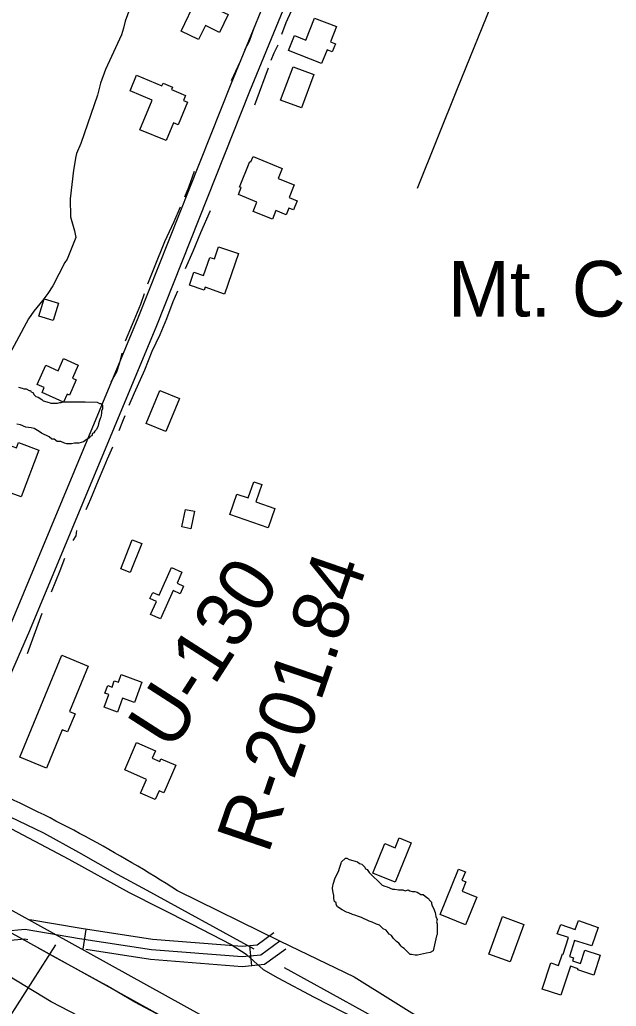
# Model space of a CAD drawing. Extents: x 3329332 to 3367211, y 631066 to 656469.
# Drawn here: x 3345355 to 3346246, y 646368 to 647841 of the extents above; entities that cross this region are included whole.
import ezdxf

# ---------------------------------------------------------------- set-up
doc = ezdxf.new("R2010")
doc.units = 0
for name, color, linetype in [('V-BLDG-OTLN', 7, 'Continuous'), ('V-FLOD-BASE', 7, 'Continuous'), ('V-LEVE-TOET', 7, 'Continuous'), ('V-RIVR-EDGE', 7, 'Continuous'), ('V-RIVR-RANG', 7, 'Continuous'), ('V-RIVR-RANG-IDEN', 7, 'Continuous'), ('V-ROAD-CNTR', 7, 'Continuous'), ('V-SITE-OTLN-IDEN', 7, 'Continuous'), ('V-SITE-VEGE', 7, 'Continuous'), ('V-SURV-LINE', 7, 'Continuous'), ('V-TOPO-SHOR', 7, 'Continuous')]:
    doc.layers.add(name, color=color, linetype=linetype)

msp = doc.modelspace()

# ---------------------------------------------------------------- linework, layer by layer
at = {"layer": 'V-BLDG-OTLN'}
for points in [[(3345595.9, 647824), (3345618.7, 647871.7), (3345666.3, 647848.9), (3345653.6, 647822.4), (3345632.2, 647832.6), (3345622.1, 647811.5)], [(3345756.7, 647795.1), (3345765.5, 647817.6), (3345782.6, 647810.9), (3345795.5, 647843.8), (3345828.1, 647831), (3345819.1, 647808.2), (3345826.5, 647805.3), (3345821.9, 647793.4), (3345814, 647796.4), (3345806, 647775.8)], [(3345744.7, 647721.2), (3345763.2, 647770.9), (3345794.5, 647759.3), (3345776, 647709.6)], [(3345534.5, 647677), (3345552.9, 647721.1), (3345519.8, 647735), (3345529.5, 647758.2), (3345567.3, 647742.4), (3345569, 647746.3), (3345583.3, 647740.3), (3345581.8, 647736.9), (3345602.6, 647728.2), (3345599.4, 647720.5), (3345605.7, 647717.9), (3345591.6, 647684.2), (3345584.7, 647687.1), (3345573.6, 647660.6)], [(3345703.5, 647636.9), (3345747.2, 647619.2), (3345741.1, 647604.1), (3345765, 647594.4), (3345757.4, 647575.6), (3345769.5, 647570.7), (3345764.1, 647557.1), (3345757.1, 647559.9), (3345753.1, 647549.7), (3345737.4, 647556.1), (3345732.4, 647543.5), (3345703.9, 647555), (3345709.4, 647568.8), (3345681.6, 647580), (3345685.8, 647590.4), (3345683.4, 647591.3), (3345698.8, 647629.4), (3345700.2, 647628.8)], [(3345681.9, 647491.8), (3345661, 647431.5), (3345631.9, 647441.6), (3345630.4, 647437.1), (3345608.3, 647444.8), (3345615.1, 647464.4), (3345629.5, 647459.4), (3345638.9, 647486.3), (3345645.8, 647483.9), (3345652.1, 647502.2)], [(3345391.3, 647424.1), (3345412.6, 647417.7), (3345404.9, 647392.1), (3345383.6, 647398.6)], [(3345412.4, 647316.9), (3345420.4, 647335), (3345442.3, 647325.3), (3345433.7, 647305.8), (3345439.4, 647303.3), (3345429.3, 647280.5), (3345425.6, 647282.1), (3345420.3, 647270.1), (3345388.2, 647284.3), (3345391.6, 647291.9), (3345381.1, 647296.5), (3345393.8, 647325.1)], [(3345543.9, 647238.1), (3345564.4, 647287.4), (3345593.6, 647275.3), (3345573.2, 647226)], [(3345383.2, 647198.5), (3345357, 647128.3), (3345325.5, 647140), (3345332.9, 647160), (3345306.5, 647169.8), (3345322.1, 647211.8), (3345349.9, 647201.5), (3345352.9, 647209.7)], [(3345726.3, 647082.4), (3345668.7, 647102.2), (3345679.2, 647132.7), (3345696.3, 647126.8), (3345704.7, 647151.1), (3345716.8, 647146.9), (3345707.9, 647121.1), (3345736.2, 647111.3)], [(3345597.1, 647083.6), (3345602.4, 647109.7), (3345615.8, 647107), (3345610.5, 647080.9)], [(3345505.8, 647021), (3345523, 647064.4), (3345537.3, 647058.7), (3345520, 647015.3)], [(3345563.2, 646981.5), (3345581.7, 647022.9), (3345597.3, 647015.9), (3345589.9, 646999.4), (3345599.8, 646995), (3345594.7, 646983.6), (3345584, 646988.4), (3345565.1, 646946.1), (3345550.4, 646952.6), (3345559.2, 646972.3), (3345549.5, 646976.6), (3345553.6, 646985.8)], [(3345394.7, 646723.3), (3345354.9, 646739.7), (3345417.8, 646891.8), (3345457.3, 646875.4), (3345429.3, 646807.9), (3345437.5, 646804.5), (3345426.3, 646777.3), (3345418.4, 646780.6)], [(3345526.2, 646821.2), (3345508.5, 646827.7), (3345500.9, 646806.8), (3345480.9, 646814.1), (3345487.8, 646833.1), (3345482.1, 646835.2), (3345486.3, 646846.7), (3345492.8, 646844.4), (3345496.2, 646853.8), (3345502.2, 646851.6), (3345506.3, 646862.9), (3345537.3, 646851.7)], [(3345511.7, 646720.5), (3345529.4, 646761.5), (3345557.7, 646749.3), (3345552.9, 646738), (3345564, 646733.2), (3345565.8, 646737.3), (3345588.2, 646727.6), (3345570.4, 646686.2), (3345563.1, 646689.4), (3345557.4, 646676.2), (3345535.2, 646685.7), (3345544.2, 646706.5)], [(3345939.9, 646611.5), (3345916, 646552.7), (3345882.3, 646566.3), (3345900.3, 646610.7), (3345915.9, 646604.3), (3345921.8, 646618.9)], [(3346021, 646489.1), (3345982.9, 646504.6), (3346010.4, 646572.4), (3346020.8, 646568.2), (3346015.7, 646555.7), (3346021.6, 646553.3), (3346016, 646539.6), (3346037.9, 646530.6)], [(3346087.5, 646433.9), (3346056, 646445.4), (3346076.3, 646501.4), (3346107.9, 646489.9)], [(3346163.6, 646384.1), (3346135.7, 646393.1), (3346148.4, 646432.3), (3346160.1, 646428.5), (3346165.7, 646445.8), (3346166.8, 646445.4), (3346174.9, 646470.3), (3346157.9, 646475.8), (3346163.5, 646489.9), (3346184.7, 646482.2), (3346189.9, 646495.5), (3346219.3, 646485.1), (3346209.5, 646457.6), (3346184, 646465.7), (3346176.3, 646441.9), (3346182.2, 646440), (3346180.7, 646435.3), (3346193, 646431.3), (3346199.5, 646451.1), (3346222.3, 646443.7), (3346212.7, 646414.1), (3346188.9, 646421.8), (3346189.5, 646423.7), (3346178, 646427.4)]]:
    msp.add_lwpolyline(points, close=True, dxfattribs=at)
at = {"layer": 'V-FLOD-BASE'}
msp.add_lwpolyline([(3345971.6, 646127.4), (3345909.1, 646161.1), (3345857.8, 646190), (3345825.7, 646208.1), (3345785.5, 646230.8), (3345742.8, 646253.7), (3345700.7, 646277.5), (3345652.9, 646304.2), (3345609.7, 646328.3), (3345567.3, 646352.1), (3345527.1, 646373.9), (3345484.7, 646398.5), (3345442.5, 646421.7), (3345405.4, 646442.1), (3345383.1, 646454.1)], dxfattribs=at)
at = {"layer": 'V-LEVE-TOET'}
for points in [[(3344834.3, 646854.9), (3344928.7, 646816.3), (3345026.5, 646776.4), (3345141, 646726.4), (3345244.3, 646681.5), (3345325.3, 646641.7), (3345428, 646587.3), (3345518.4, 646537.4), (3345612.2, 646490.4), (3345670.8, 646459.7), (3345693.1, 646445.6), (3345704.9, 646434.9), (3345718.8, 646422.5), (3345740.5, 646410), (3345794.7, 646381.1), (3345903, 646326.1), (3345989.5, 646277.3)], [(3346013.7, 646039.7), (3345895.4, 646104.8), (3345803.9, 646154.7), (3345690, 646221.5), (3345619.1, 646261.2), (3345512.5, 646316.8), (3345402, 646374.1), (3345325.5, 646420.5), (3345293.7, 646439.2), (3345274.2, 646444.9), (3345256.3, 646453.4), (3345249.6, 646458.5), (3345237.4, 646472), (3345175.4, 646506.6), (3345048.1, 646563.4), (3344965.9, 646595.9), (3344884.9, 646632.8), (3344779.4, 646679.4), (3344684.4, 646718.1), (3344578.8, 646760.2), (3344535.2, 646780.7), (3344440.3, 646822.7)]]:
    msp.add_lwpolyline(points, dxfattribs=at)
at = {"layer": 'V-RIVR-EDGE'}
msp.add_spline([(3345726.6, 645695.4), (3345710.3, 645706.7), (3345706, 645707.1), (3345696.7, 645709.8), (3345683.6, 645718), (3345672.7, 645726.9), (3345658.8, 645738.2), (3345648.7, 645743.7), (3345639.4, 645746), (3345632.9, 645748), (3345603.4, 645766.6), (3345581.4, 645780.7), (3345572.4, 645785), (3345555.4, 645793.9), (3345546.1, 645800.1), (3345532.6, 645806), (3345524, 645813.4), (3345515.1, 645817.3), (3345499.6, 645821.6), (3345480.7, 645830.6), (3345474.1, 645837.5), (3345464.8, 645841.1), (3345450.4, 645846.1), (3345438, 645851.6), (3345424.9, 645858.2), (3345414.4, 645862.1), (3345403.2, 645866), (3345391.6, 645870.3), (3345367.9, 645880.1), (3345352, 645885.9), (3345338.1, 645891), (3345321.8, 645896.5), (3345300.5, 645902.7), (3345290.8, 645905.5), (3345275.7, 645907.8), (3345235.8, 645916.1), (3345209, 645924.7), (3345182.3, 645936.4), (3345156.4, 645950.4), (3345125.4, 645971), (3345109.5, 645981.9), (3345099.8, 645991.7), (3345083.6, 646002.6), (3345079.7, 646004.1), (3345072, 646007.6), (3345058.4, 646015.4), (3345047.2, 646021.6), (3345036.7, 646027.5), (3345031.3, 646033.3), (3345026.7, 646039.1), (3345021.2, 646043.8), (3344994.5, 646058.6), (3344983.7, 646064.9), (3344981.8, 646070.7), (3344976.7, 646076.1), (3344962, 646083.1), (3344939.9, 646096.8), (3344923.3, 646108), (3344901.6, 646122.8), (3344889.6, 646131.4), (3344869.1, 646144.2), (3344864.4, 646148.5), (3344847.8, 646159.4), (3344817.2, 646179.7), (3344808.7, 646184.3), (3344794.7, 646192.1), (3344773.1, 646202.7), (3344760.3, 646211.6), (3344744.4, 646224.1), (3344736.7, 646231.4), (3344732.8, 646234.9), (3344710.7, 646245.9), (3344691.8, 646256.8), (3344677.4, 646263.4), (3344663.5, 646270.4), (3344646.4, 646279.8), (3344631.7, 646288.3), (3344630.6, 646291), (3344624, 646294.9), (3344606.2, 646307.4), (3344563.2, 646333.1), (3344534.5, 646350.2), (3344492.3, 646375.9), (3344459, 646398.5), (3344451.3, 646403.9), (3344437.7, 646412.5), (3344413.7, 646427.7), (3344366.5, 646453.4), (3344331.6, 646475.2), (3344310, 646488.1), (3344300.7, 646492), (3344285.5, 646499), (3344268.5, 646506.8), (3344249.9, 646518.8), (3344243.7, 646523.9), (3344230.2, 646531.3), (3344213.9, 646541), (3344196.9, 646551.5), (3344176, 646564.4), (3344151.2, 646577.3), (3344146.9, 646581.5), (3344142.3, 646583.9), (3344134.5, 646585.1), (3344108.6, 646594.8), (3344078.7, 646610.4), (3344072.1, 646611.2), (3344057.8, 646616.7), (3344035, 646628.3), (3344016.8, 646636.5), (3343997, 646644), (3343970.7, 646656.8), (3343940.1, 646674), (3343908.3, 646692.6), (3343880.4, 646708.2), (3343858, 646717.6), (3343833.5, 646728.5), (3343826.2, 646734.3), (3343820, 646736.7), (3343805.3, 646741.8), (3343796, 646746.1), (3343784.7, 646753.8), (3343774.3, 646760.8), (3343754.5, 646769.8), (3343741, 646776.1), (3343736.3, 646780.7), (3343730.5, 646785.8), (3343725.9, 646790), (3343710.4, 646800.2), (3343695.7, 646809.9), (3343682.9, 646818.9), (3343675.9, 646822), (3343662.8, 646826.3), (3343657.7, 646828.6), (3343655.8, 646833.3), (3343653.9, 646835.6), (3343636.8, 646843.4)], degree=3, dxfattribs=at)
at = {"layer": 'V-RIVR-RANG'}
msp.add_line((3345408.3, 646459.5), (3344790.5, 645492), dxfattribs=at)
at = {"layer": 'V-ROAD-CNTR'}
for p, q in [((3345449.7, 646452.7), (3345454.2, 646482.3)), ((3345701.7, 646428), (3345698.9, 646457.9))]:
    msp.add_line(p, q, dxfattribs=at)
for points in [[(3345245.2, 646719.2), (3345342.6, 646940.9), (3345531.9, 647395.7), (3345671, 647745.7), (3345827.4, 648126.6), (3345886.5, 648265.7), (3346017.4, 648601.1), (3346078.6, 648752.7)], [(3345272.6, 646707.1), (3345370.2, 646929.1), (3345559.7, 647384.3), (3345698.8, 647734.4), (3345855.1, 648115), (3345914.3, 648254.4), (3346045.2, 648590.1), (3346106.5, 648741.5)], [(3345589.9, 646540.5), (3345744, 646464.8), (3345854.6, 646411.3), (3346087.5, 646266.3), (3346355.6, 646117.9), (3346605.3, 645982.1), (3346861.1, 645840.8), (3347152.9, 645675.5), (3347384.7, 645545.3), (3347693.4, 645361.8), (3347955.1, 645199.7), (3348151.9, 645081.3), (3348306.9, 644982.2), (3348487.1, 644875.2), (3348654.8, 644770.2), (3348825.3, 644661.9), (3349015.2, 644543.5), (3349310.2, 644344.7), (3349498.5, 644223.3), (3349706.2, 644088.4), (3349830.5, 644007.7), (3350058.3, 643841.5), (3350137, 643783.8), (3350319.4, 643639.9)], [(3345734.6, 646477.2), (3345709.5, 646458.9), (3345687.2, 646456.7), (3345553.5, 646467.1), (3345446.6, 646483.5), (3345370, 646496.7)], [(3345030.1, 646216.5), (3345169.1, 646418.5), (3345203.8, 646459.9), (3345221.3, 646469), (3345254.7, 646474.8), (3345297.9, 646476.7), (3345363.1, 646482.7), (3345444.2, 646468.7), (3345551.8, 646452.2), (3345687.3, 646441.7), (3345715.1, 646444.3), (3345743.5, 646465.1)], [(3345366.8, 646466.8), (3345362.5, 646467.6), (3345298.9, 646461.7), (3345256.3, 646459.9), (3345226.2, 646454.6), (3345213.4, 646448), (3345181.1, 646409.4), (3345042.4, 646208)], [(3345752.3, 646453), (3345720.6, 646429.8), (3345687.4, 646426.6), (3345550.1, 646437.3), (3345453.4, 646452.1)]]:
    msp.add_lwpolyline(points, dxfattribs=at)
msp.add_arc((3344438.6, 644743.8), 2133.9, 57.3299, 65.895, dxfattribs=at)
at = {"layer": 'V-SITE-VEGE'}
for points in [[(3345536.1, 647904.1), (3345512.2, 647839.1), (3345510, 647828.8), (3345506.7, 647818.5), (3345483.1, 647767), (3345475.5, 647746.4), (3345471.1, 647728.8), (3345446.1, 647656.6), (3345439.6, 647641.2), (3345438.5, 647637), (3345435, 647616.3), (3345430.2, 647573.9), (3345430.8, 647546.9), (3345436.7, 647526.1), (3345438.6, 647515.7), (3345425.7, 647483.7), (3345422.5, 647478.6), (3345404.3, 647443.6), (3345396.8, 647432.3), (3345389.4, 647422.1), (3345375.7, 647405.7), (3345368.2, 647394.4), (3345328.7, 647321.4)], [(3345353.1, 647292.2), (3345358.7, 647291.1), (3345360.9, 647289.9), (3345364.3, 647289.9), (3345368.8, 647287.6), (3345371, 647287.6), (3345372.1, 647285.4), (3345374.4, 647284.2), (3345376.6, 647280.9), (3345378.8, 647278.6), (3345382.2, 647277.5), (3345387.7, 647274.1), (3345390, 647271.8), (3345398.9, 647269.5), (3345401.1, 647268.4), (3345411.2, 647268.3), (3345414.6, 647269.4), (3345416.8, 647269.4), (3345420.2, 647270.5), (3345452.7, 647270.3), (3345470.6, 647270.2), (3345474, 647267.9), (3345476.2, 647267.9), (3345478.4, 647265.6), (3345478.4, 647260), (3345477.2, 647256.7), (3345477.2, 647253.3), (3345476.1, 647247.7), (3345474.9, 647245.5), (3345473.8, 647241), (3345472.6, 647237.7), (3345471.5, 647233.2), (3345469.2, 647228.7), (3345467, 647226.5), (3345465.8, 647224.3), (3345463.6, 647223.2), (3345462.4, 647219.8), (3345460.2, 647218.7), (3345459.1, 647216.5), (3345454.6, 647214.3), (3345452.3, 647212), (3345450.1, 647210.9), (3345443.3, 647208.7), (3345436.6, 647208.8), (3345432.1, 647207.7), (3345425.4, 647207.7), (3345422, 647208.9), (3345416.5, 647211.1), (3345410.9, 647211.2), (3345406.4, 647214.6), (3345403, 647214.6), (3345398.6, 647218), (3345387.4, 647223.7), (3345384.1, 647225.9), (3345376.3, 647230.4), (3345371.8, 647231.6), (3345363.9, 647232.8), (3345356.1, 647236.2), (3345350.5, 647237.3)]]:
    msp.add_lwpolyline(points, dxfattribs=at)
msp.add_lwpolyline([(3345977.6, 646493.9), (3345978.7, 646490.6), (3345978.6, 646474.9), (3345977.5, 646472.7), (3345972.8, 646450.3), (3345968.3, 646448.1), (3345962.7, 646447), (3345949.3, 646443.7), (3345945.9, 646443.7), (3345940.3, 646444.9), (3345938.1, 646444.9), (3345929.2, 646453.9), (3345926.9, 646455.1), (3345924.7, 646457.3), (3345921.4, 646461.8), (3345918, 646464.1), (3345913.6, 646468.6), (3345910.2, 646473.1), (3345906.9, 646475.3), (3345902.5, 646481), (3345898, 646483.2), (3345892.4, 646488.9), (3345888, 646490), (3345881.3, 646493.4), (3345876.8, 646494.6), (3345865.6, 646500.3), (3345861.1, 646501.4), (3345855.5, 646503.7), (3345852.2, 646504.8), (3345846.6, 646507.1), (3345843.3, 646508.2), (3345836.6, 646511.6), (3345829.9, 646516.2), (3345827.6, 646519.5), (3345827.7, 646521.8), (3345825.4, 646524), (3345824.3, 646528.5), (3345824.4, 646533), (3345823.3, 646537.5), (3345822.2, 646543.1), (3345822.2, 646544.6), (3345822.5, 646547), (3345823.2, 646550.1), (3345826.3, 646559.2), (3345831, 646569.1), (3345833.1, 646575.4), (3345834.7, 646579.6), (3345835.1, 646581.5), (3345835.9, 646583.3), (3345841.5, 646588.9), (3345843.8, 646588.9), (3345847.1, 646586.6), (3345852.7, 646585.5), (3345859.4, 646583.2), (3345862.8, 646580.9), (3345866.1, 646579.8), (3345870.6, 646575.3), (3345871.7, 646573), (3345873.9, 646571.9), (3345877.2, 646567.4), (3345896.2, 646548.2), (3345900.6, 646547.1), (3345904, 646545.9), (3345911.8, 646542.5), (3345915.2, 646542.5), (3345920.8, 646541.4), (3345927.5, 646541.3), (3345930.8, 646540.2), (3345935.3, 646541.3), (3345937.6, 646540.1), (3345942, 646539), (3345945.4, 646539), (3345948.8, 646537.8), (3345951, 646536.7), (3345954.3, 646534.4), (3345957.7, 646534.4), (3345963.3, 646529.9), (3345965.5, 646528.7), (3345966.6, 646526.5), (3345969.9, 646523.1), (3345969.9, 646520.9), (3345971, 646517.5), (3345973.2, 646514.1), (3345975.4, 646507.4), (3345976.5, 646501.8), (3345978.7, 646497.3)], close=True, dxfattribs=at)
at = {"layer": 'V-SURV-LINE'}
for points in [[(3345209, 646584.8), (3347329.4, 645411.7)], [(3347314.9, 645385.4), (3345194.5, 646558.5)]]:
    msp.add_lwpolyline(points, dxfattribs=at)
at = {"layer": 'V-TOPO-SHOR'}
for p, q in [((3345671.5, 647750.3), (3345684.3, 647778.2)), ((3345366.3, 646894.4), (3345388.6, 646955))]:
    msp.add_line(p, q, dxfattribs=at)
for points in [[(3346718.9, 649476.9), (3346672.5, 649362.3), (3346595.6, 649177.3), (3346507.3, 648960), (3346442.3, 648799.8), (3346354.7, 648584.4), (3346260.6, 648361.5), (3346184.9, 648170.7), (3346099.4, 647968.1), (3346064.8, 647876.8), (3346008.4, 647738.1), (3345948.6, 647589.2)], [(3345746.7, 647819.5), (3345753.2, 647837.1), (3345760.9, 647854.7), (3345769.4, 647872.6)], [(3345691.4, 647796.1), (3345698.4, 647809.2), (3345705.9, 647830.7)], [(3345730.8, 647781), (3345735.3, 647791.6), (3345741, 647803.6)], [(3345706, 647714.2), (3345713.3, 647732.9), (3345721.6, 647755.8), (3345726.5, 647769.2)], [(3345601.5, 647576.8), (3345607.7, 647591), (3345616, 647615.1)], [(3345546.3, 647446.6), (3345556.2, 647471.8), (3345571.9, 647510), (3345585.8, 647539.9), (3345594.9, 647561.7)], [(3345602.7, 647469.5), (3345613.8, 647495.5), (3345625.4, 647523.4), (3345640, 647556.1)], [(3345518.5, 647265.6), (3345526.2, 647284), (3345541.8, 647318.1), (3345552.9, 647346), (3345564.5, 647370.9), (3345574.5, 647394.9), (3345584.2, 647420.3), (3345591.1, 647436.3)], [(3345513, 647361.4), (3345523.2, 647386.6), (3345536, 647416.4), (3345541.2, 647432.1)], [(3345491.3, 647300.5), (3345499.8, 647315.3), (3345504.6, 647329.3), (3345507.8, 647343)], [(3345503.2, 647227.6), (3345509.1, 647241.6), (3345512.3, 647250.2)], [(3345454, 647109.5), (3345461.3, 647125.7), (3345472.4, 647153.3), (3345481.2, 647173.4), (3345485.8, 647185.2), (3345493.8, 647203)], [(3345434.6, 647063.1), (3345439.1, 647070.3), (3345440, 647078.2)], [(3345402.2, 646986.8), (3345409, 647002.5), (3345415.5, 647018.7), (3345422.1, 647036.8)], [(3345339.8, 646650.8), (3345390.3, 646626.4), (3345442.8, 646597.5), (3345500.6, 646564.9), (3345544.7, 646541.1), (3345704.6, 646453.4)], [(3345749.9, 646425.2), (3345818.7, 646387.8), (3345871.2, 646358.9), (3345915.6, 646334.5), (3345958, 646310.7)]]:
    msp.add_lwpolyline(points, dxfattribs=at)

# ---------------------------------------------------------------- texts
at = {"layer": 'V-RIVR-RANG-IDEN'}
for s, rotation, p in [('R-201.84', 71.041, (3345726, 646593.4)), ('U-130', 57.2973, (3345582.1, 646746.5))]:
    msp.add_text(s, height=83, rotation=rotation, dxfattribs=at).set_placement(p)
at = {"layer": 'V-SITE-OTLN-IDEN'}
msp.add_text('Mt. Carmel Ch.', height=83, dxfattribs=at).set_placement((3345994.8, 647397.9))

doc.saveas('drawing.dxf')
